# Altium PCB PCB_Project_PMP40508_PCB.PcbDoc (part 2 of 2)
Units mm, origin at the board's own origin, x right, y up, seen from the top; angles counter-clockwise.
Board outline 120 x 67 mm, 2 copper layers (Top Layer, Bottom Layer), stack 1.575 mm thick; 78 components, 43 nets, 177 pads, 0 vias.
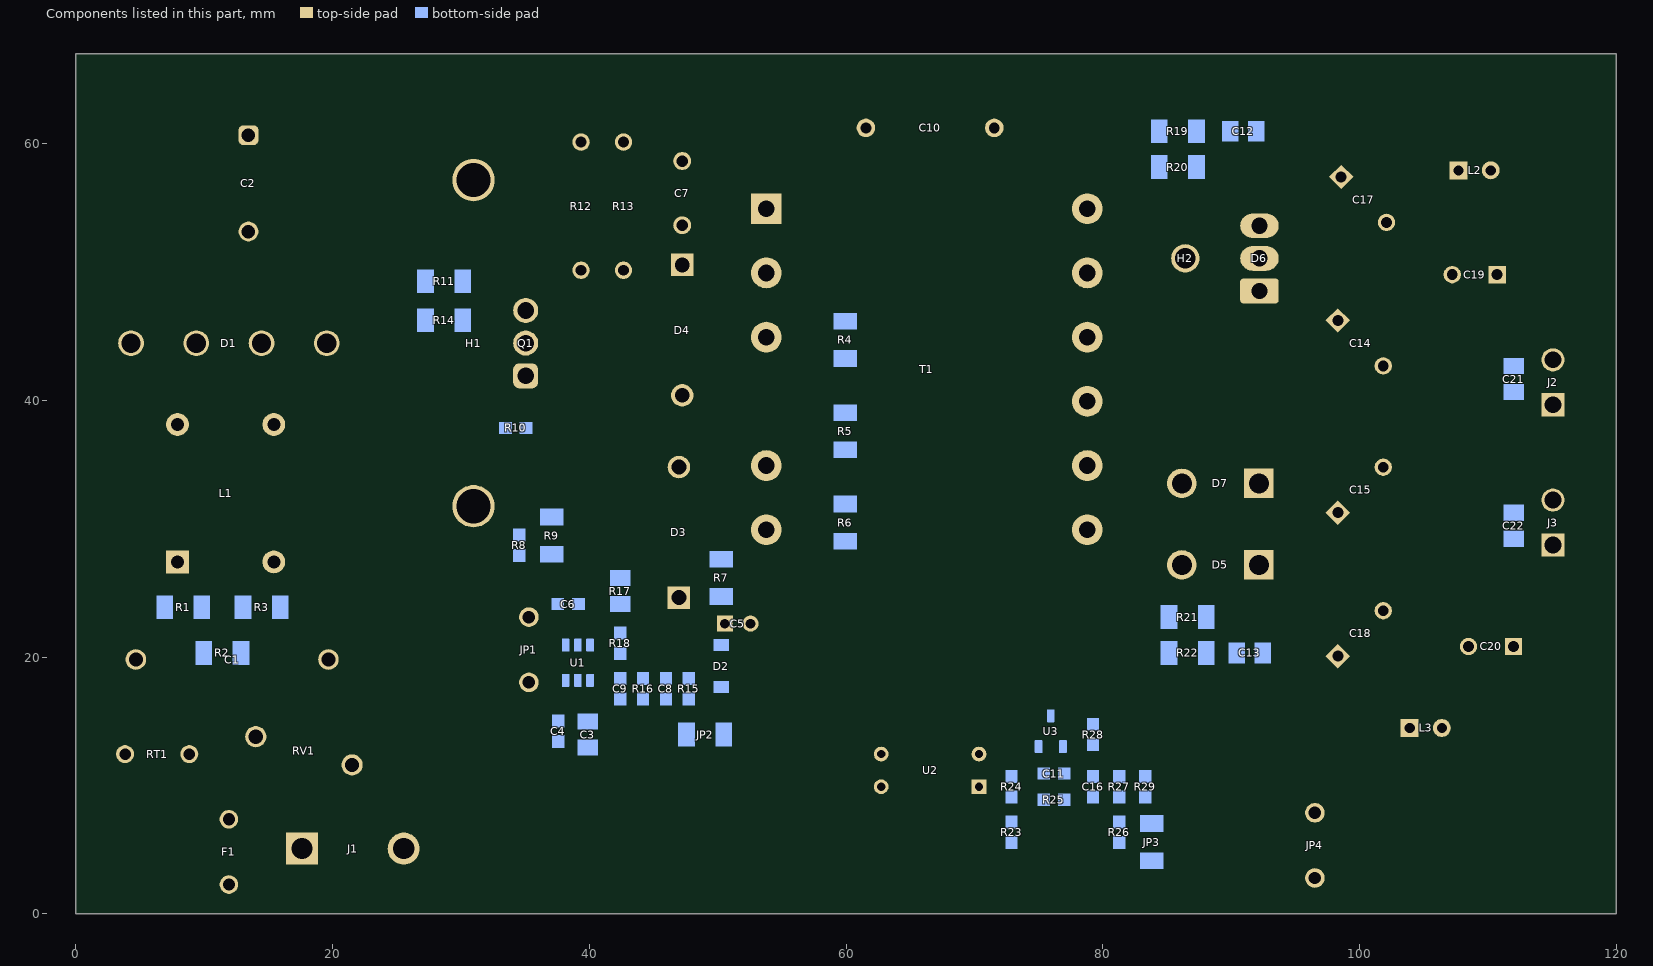
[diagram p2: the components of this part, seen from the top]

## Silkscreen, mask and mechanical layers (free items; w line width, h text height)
Top Overlay:
  text "VOUT2" at 112.776,45.466 h1.85
  text "GND" at 113.284,35.306 h1.85
  text "VOUT1" at 112.776,24.638 h1.85
  text "L" at 17.526,10.16 h1.85
  text "N" at 24.892,10.16 h1.85
  text "PMP40508 Rev. 1.0" at 40.132,5.08 h2.5
  text ".Layer_Name" at 14.656,-21.806 h1.52
Bottom Overlay:
  circle w0.254: c5,62 r3.5
  circle w0.254: c115,62 r3.5
  circle w0.254: c115,5 r3.5
  circle w0.254: c5,5 r3.5
  text ".Layer_Name" at 14.656,-21.806 h1.52
Top Paste:
  text ".Layer_Name" at 14.656,-21.806 h1.52
Bottom Paste:
  text ".Layer_Name" at 14.656,-21.806 h1.52
Top Solder:
  text ".Layer_Name" at 14.656,-21.806 h1.52
  text ".Layer_Name" at 14.656,-21.806 h1.52
Bottom Solder:
  text ".Layer_Name" at 14.656,-21.806 h1.52
Drill Guide:
  text ".Layer_Name" at 14.656,-21.806 h1.52
M1 Board Outline:
  lines w0.152: 32.512,42.926 37.338,42.926 37.338,43.434 32.512,43.434 32.512,42.926 ; 32.512,45.466 32.512,45.974 37.338,45.974 37.338,45.466 32.512,45.466 ; 66.04,6.096 67.056,6.096 67.056,16.256 66.04,16.256 66.04,6.096
  lines w0.254: 0,0 0,67 120,67 120,0 0,0
  text ".Layer_Name" at 14.656,-21.806 h1.52
M2 Board Dimensions:
  rectangle: 0,-6.985 3.175,-3.81
  rectangle: 3.175,-10.16 12.7,-6.985
  lines w0.178: 0,-6.985 25.4,-6.985 ; 3.175,-10.16 3.175,-3.81 ; 6.35,-10.16 6.35,-3.81 ; 12.7,-10.16 12.7,-3.81 ; 19.05,-10.16 19.05,-3.81 ; 0,-10.16 25.4,-10.16 25.4,-3.81 0,-3.81 0,-10.16
  text ".Layer_Name" at 14.656,-21.806 h1.52
M3 3D STEP Top:
  text ".Layer_Name" at 14.656,-21.806 h1.52
M4 3D STEP Bottom:
  text ".Layer_Name" at 14.656,-21.806 h1.52
M5 Assembly Top:
  lines w0.254: -7.417,-23.626 160.223,-23.626 ; -7.417,-18.462 160.274,-18.462 ; -7.417,-13.297 -7.417,-28.791 94.31,-28.791 160.274,-28.791 160.274,-13.297 -7.404,-13.297 -7.404,-28.791 32.614,-28.791 ; 55.194,-28.791 55.194,-13.297 ; 87.376,-18.462 87.376,-13.297 ; 108.712,-18.462 108.712,-13.297 ; 124.511,-28.956 124.511,-23.804
  text "COMPONENTS MARKED 'DNP' SHOULD NOT BE POPULATED." at 29.299,-8.09 h1.52
  text "ASSEMBLY VARIANT:" at 29.286,-11.024 h1.52
  text ".VariantName" at 55.601,-11.024 h1.52
  text "PCB VIEWED FROM TOP SIDE" at -5.804,-16.654 h1.52
  text "BOARD #:" at 57.099,-16.654 h1.52
  text ".PRJ_Number" at 70.955,-16.654 h1.52
  text "REV:" at 92.405,-16.654 h1.52
  text ".PCB_Rev" at 99.809,-16.654 h1.52
  text "SVN REV:" at 113.69,-16.654 h1.52
  text ".VersionControl_RevNumber" at 126.543,-16.654 h1.52
  text "TID #:" at 57.099,-21.819 h1.52
  text ".TID" at 70.955,-21.819 h1.52
  text "PLOT NAME =" at -5.804,-27.034 h1.52
  text ".plot_File_Name" at 14.656,-27.034 h1.52
  text "GENERATED    :" at 57.15,-27.034 h1.52
  text ".Print_Date" at 79.235,-27.034 h1.52
  text ".Print_Time" at 97.752,-27.034 h1.52
  text "TEXAS INSTRUMENTS" at 129.87,-27.034 h1.52
M6 Assembly Bottom:
  lines w0.254: -7.429,-18.474 160.261,-18.474 ; -7.379,-23.639 160.261,-23.639 ; 28.334,-28.969 28.334,-23.817 ; 44.133,-18.474 44.133,-13.31 ; 65.468,-18.474 65.468,-13.31 ; 97.65,-28.804 97.65,-13.31 ; 120.231,-28.804 160.249,-28.804 160.249,-13.31 -7.429,-13.31 -7.429,-28.804 58.534,-28.804 160.261,-28.804 160.261,-13.31
  text "COMPONENTS MARKED 'DNP' SHOULD NOT BE POPULATED." at 154.991,-8.077 h1.52
  text ".VariantName" at 128.473,-11.024 h1.52
  text "ASSEMBLY VARIANT:" at 154.864,-11.024 h1.52
  text ".VersionControl_RevNumber" at 26.302,-16.667 h1.52
  text "SVN REV:" at 39.154,-16.667 h1.52
  text ".PCB_Rev" at 53.035,-16.667 h1.52
  text "REV:" at 60.439,-16.667 h1.52
  text ".PRJ_Number" at 81.89,-16.667 h1.52
  text "BOARD #:" at 95.745,-16.667 h1.52
  text "PCB VIEWED FROM BOTTOM SIDE" at 158.648,-16.667 h1.52
  text ".TID" at 81.89,-21.831 h1.52
  text "TID #:" at 95.745,-21.831 h1.52
  text "TEXAS INSTRUMENTS" at 22.974,-27.047 h1.52
  text ".Print_Time" at 55.093,-27.047 h1.52
  text ".Print_Date" at 73.609,-27.047 h1.52
  text "GENERATED    :" at 95.694,-27.047 h1.52
  text ".plot_File_Name" at 138.189,-27.047 h1.52
  text "PLOT NAME =" at 158.648,-27.047 h1.52
M9 Title Sheet:
  drawing of 57 lines, arcs and shapes, not listed
  text "1" at 18.792,204.127 h1.78
  text "2" at 82.182,204.127 h1.78
  text "3" at 145.411,204.127 h1.78
  text "4" at 209.08,204.127 h1.78
  text "5" at 272.555,204.127 h1.78
  text "6" at 336.182,204.127 h1.78
  text "A" at -10.579,175.095 h1.78
  text "A" at 365.341,175.095 h1.78
  text "B" at -10.579,114.643 h1.78
  text "B" at 365.341,114.643 h1.78
  text "C" at -10.579,54.318 h1.78
  text "C" at 365.341,54.318 h1.78
  text "PROJECT TITLE:" at 288.125,7.048 h1.14
  text ".PRJ_Title" at 289.395,3.662 h1.78
  text "DESIGNED FOR:" at 288.125,-0.597 h1.14
  text ".PRJ_Customer" at 289.395,-4.153 h1.78
  text "D" at -10.579,-5.88 h1.78
  text "D" at 365.341,-5.88 h1.78
  text "FILE NAME:" at 288.125,-8.217 h1.14
  text ".PCB_File_Name_No_Path" at 289.395,-11.265 h1.78
  text "Texas Instruments (TI) and/or its licensors do not warrant the accuracy or completeness of this specification" at 161.9,-15.376 h1.14
  text "ENGINEER:" at 288.125,-15.583 h1.14
  text "LAYOUT BY:" at 326.352,-15.583 h1.14
  text "or any information contained therein. TI and/or its licensors do not warrant that this design will meet" at 160.757,-18.237 h1.14
  text ".PRJ_Engineer" at 289.395,-19.52 h1.78
  text ".PCB_Layout" at 327.635,-19.52 h1.78
  text "the specifications, will be suitable for your application or fit for any particular purpose, or will operate in" at 160.757,-21.099 h1.14
  text ".Layer_Name" at 14.656,-21.806 h1.52
  text "ALTIUM DESIGNER VERSION:" at 326.352,-23.457 h1.14
  text "an implementation. TI and/or its licensors do not warrant that the design is production worthy. You should" at 160.757,-23.961 h1.14
  text "completely validate and test your design implementation to confirm the system functionality for your application." at 161.9,-26.822 h1.14
  text ".print_Scale" at 289.395,-26.843 h1.78
  text ".Application_BuildNumber" at 327.635,-26.843 h1.78
  text "1" at 18.792,-32.093 h1.78
  text "2" at 82.182,-32.093 h1.78
  text "3" at 145.411,-32.093 h1.78
  text "4" at 209.08,-32.093 h1.78
  text "5" at 272.555,-32.093 h1.78
  text "6" at 336.182,-32.093 h1.78
M10 Fab Notes:
  drawing of 189 lines, arcs and shapes, not listed
  text "DESIGN INFORMATION" at 314.503,161.447 h1.52
  text "MIN. TRACK WIDTH:" at 298.131,158.091 h1.52
  text "8" at 325.976,158.091 h1.52
  text "MIL" at 329.907,158.091 h1.52
  text "MIN. CLEARANCE:" at 298.131,154.938 h1.52
  text "0.2" at 324.452,154.938 h1.52
  text "mm" at 329.907,154.938 h1.52
  text "MIN. VIA PAD SIZE:" at 298.131,151.785 h1.52
  text "24" at 325.214,151.785 h1.52
  text "MIL" at 329.907,151.785 h1.52
  text "0.05mm (2MIL)" at 315.784,148.486 h1.52
  text "MINIMUM ANNULAR RING" at 289.769,148.277 h1.52
  text "EXTERNAL" at 333.768,148.277 h1.52
  text "PER" at 294.849,145.48 h1.52
  text "IPC-D-275 CLASS 2 LEVEL C" at 300.437,145.48 h1.52
  text "MIL, HOLES" at 338.238,142.928 h1.52
  text "+/-" at 328.27,142.709 h1.52
  text "+/-" at 349.961,142.709 h1.52
  text "REGISTRATION TOLERANCES:" at 289.769,142.682 h1.52
  text "METAL" at 320.243,142.682 h1.52
  text "5" at 334.879,142.683 h1.52
  text "3" at 356.037,142.683 h1.52
  text "MIL" at 358.99,142.682 h1.52
  text "HOLE SIZE TOLERANCE (UNLESS OTHERWISE SPECIFIED):" at 289.769,140.185 h1.52
  text "+/-" at 349.961,140.112 h1.52
  text "3" at 356.037,140.085 h1.52
  text "MIL" at 358.99,140.085 h1.52
  text "MATERIAL:" at 287.87,136.589 h1.52
  text "FR-4 High Tg" at 312.926,133.324 h1.52
  text "X" at 309.257,133.122 h1.52
  text "FR-408" at 298.563,133.007 h1.52
  text "OTHER" at 336.358,133.007 h1.52
  text "62 MIL (1.6mm) +/-10%" at 306.694,129.374 h1.52
  text "X" at 303.643,129.312 h1.52
  text "THICKNESS:" at 289.769,129.165 h1.52
  text "OTHER" at 339.33,129.165 h1.52
  text "TOLERANCE:" at 289.769,125.652 h1.52
  text "X" at 311.314,125.652 h1.52
  text "ANSI IPC-6012 TYPE 3 CLASS 2" at 315.836,125.652 h1.52
  text "OTHER +/-" at 315.835,121.989 h1.52
  text "BOW & TWIST:" at 289.769,118.302 h1.52
  text "X" at 311.314,118.302 h1.52
  text "ANSI IPC-6012 TYPE 3 CLASS 2" at 315.836,118.302 h1.52
  text "OTHER +/-" at 315.835,114.576 h1.52
  text "DRILLING:" at 287.87,111.258 h1.52
  text "NC_DRILL FILES" at 332.599,108.586 h1.52
  text "REFERENCE:" at 289.769,108.486 h1.52
  text "X" at 306.463,108.484 h1.52
  text "AS SHOWN" at 310.984,108.486 h1.52
  text "X" at 329.348,108.486 h1.52
  text "OTHER" at 340.168,104.873 h1.52
  text "PTH COPPER THICKNESS:" at 289.761,104.783 h1.52
  text "X" at 318.697,104.783 h1.52
  text "20-30 um" at 321.948,104.783 h1.52
  text "BOARD FINISH:" at 287.87,101.034 h1.52
  text "SILKSCREEN:" at 291.812,98.237 h1.52
  text "X" at 316.14,98.237 h1.52
  text "TOP" at 319.112,98.237 h1.52
  text "X" at 329.094,98.237 h1.52
  text "BOTTOM" at 332.091,98.237 h1.52
  text "SILKSCREEN COLOR:" at 291.812,94.295 h1.52
  text "X" at 316.115,94.295 h1.52
  text "WHITE" at 319.112,94.295 h1.52
  text "OTHER" at 332.091,94.295 h1.52
  text "X" at 319.442,90.652 h1.52
  text "GREEN" at 322.439,90.652 h1.52
  text "OTHER" at 338.136,90.652 h1.52
  text "SOLDER RESIST COLOR:" at 291.812,90.477 h1.52
  text "X" at 319.442,86.734 h1.52
  text "MATTE" at 322.439,86.734 h1.52
  text "SEMI-GLOSS" at 338.125,86.717 h1.52
  text "IMMERSION GOLD (ENIG)" at 314.819,82.345 h1.52
  text "ENEPIG" at 348.793,82.162 h1.52
  text "SURFACE FINISH:" at 287.87,82.136 h1.52
  text "X" at 310.298,82.136 h1.52
  text "IMM. TIN/SILVER OR EQUIV" at 296.24,78.649 h1.52
  text "OTHER" at 332.599,78.549 h1.52
  text "ARRAY/PANEL:" at 287.87,74.602 h1.52
  text "CUT AND TRIM PER M1 BOARD OUTLINE" at 314.819,74.393 h1.52
  text "N.C. ROUTE" at 314.819,70.94 h1.52
  text "X" at 332.295,70.94 h1.52
  text "V. SCORE" at 336.816,70.94 h1.52
  text "CERTIFICATION:" at 287.87,67.66 h1.52
  text "MATERIALS AND WORKMANSHIP FOR ALL PCBS" at 306.285,67.66 h1.52
  text "TO MEET OR EXCEED THE REQUIREMENTS OF:" at 306.285,65.271 h1.52
  text "X" at 297.078,62.003 h1.52
  text "ANSI IPC-A-600F CLASS ->" at 300.329,62.003 h1.52
  text "X" at 342.188,62.003 h1.52
  text "2" at 344.982,62.003 h1.52
  text "1" at 336.981,61.965 h1.52
  text "3" at 353.973,61.965 h1.52
  text "X" at 317.702,58.252 h1.52
  text "RoHS" at 320.953,58.252 h1.52
  text "OTHER" at 337.321,58.252 h1.52
  text "PER ORDER" at 347.407,58.252 h1.52
  text "ALL BOARDS MUST MEET OR EXCEED UL94-V0 REQUIREMENTS." at 288.569,54.345 h1.52
  text "PCB MUST BEAR THE UL94V-0 UL REGISTERED MATERIAL ID NUMBER" at 288.569,51.397 h1.52
  text "ADDITIONAL REQUIREMENTS:" at 287.87,47.094 h1.52
  text "MICROSECTION:" at 289.769,44.373 h1.52
  text "YES" at 312.775,44.373 h1.52
  text "REQUIRED" at 334.657,40.707 h1.52
  text "BARE BOARD ELEC. TEST:" at 289.769,40.634 h1.52
  text "NONE" at 322.935,40.634 h1.52
  text "X" at 331.66,40.634 h1.52
  text "PER ORDER" at 349.693,40.634 h1.52
  text "XX MIL VIAS REQUIRE NON-CONDUCTIVE FILL AND PLANARIZE" at 294.04,35.428 h1.5
  text "XX MIL VIAS REQUIRE CONDUCTIVE FILL AND PLANARIZE" at 294.243,32.787 h1.52
  text "OUTER XX MIL TRACES REQUIRE 50 OHM SINGLE-ENDED IMPEDANCE" at 294.218,28.637 h1.47
  text "LAYER 2 & 3 (INNER LAYERS) XX MIL WIDE, XX MIL SPACE / TRACES REQUIRE 100 OHM DIFFERENTIAL IMPEDANCE" at 294.015,22.65 h1.52
  text ".Layer_Name" at 14.656,-21.806 h1.52
M11 Gerber Information:
  lines w0.254: -7.417,-23.626 160.223,-23.626 ; -7.417,-18.462 160.274,-18.462 ; -7.417,-13.297 -7.417,-28.791 94.31,-28.791 160.274,-28.791 160.274,-13.297 -7.404,-13.297 -7.404,-28.791 32.614,-28.791 ; 55.194,-28.791 55.194,-13.297 ; 87.376,-18.462 87.376,-13.297 ; 108.712,-18.462 108.712,-13.297 ; 124.511,-28.956 124.511,-23.804
  text "ALL ARTWORK VIEWED FROM TOP SIDE" at -5.804,-16.654 h1.52
  text "BOARD #:" at 57.099,-16.654 h1.52
  text ".PRJ_Number" at 70.955,-16.654 h1.52
  text "REV:" at 92.405,-16.654 h1.52
  text ".PCB_Rev" at 99.809,-16.654 h1.52
  text "SVN REV:" at 113.69,-16.654 h1.52
  text ".VersionControl_RevNumber" at 126.543,-16.654 h1.52
  text "LAYER NAME =" at -5.804,-21.806 h1.52
  text "TID #:" at 57.099,-21.819 h1.52
  text ".TID" at 70.955,-21.819 h1.52
  text "PLOT NAME =" at -5.804,-27.034 h1.52
  text ".plot_File_Name" at 14.656,-27.034 h1.52
  text "GENERATED    :" at 57.15,-27.034 h1.52
  text ".Print_Date" at 79.235,-27.034 h1.52
  text ".Print_Time" at 97.752,-27.034 h1.52
  text "TEXAS INSTRUMENTS" at 129.87,-27.034 h1.52
M12 Stackup:
  drawing of 191 lines, arcs and shapes, not listed
  text "Layer" at 248.865,198.882 h1.52
  text "Name" at 259.277,198.882 h1.52
  text "Material" at 282.892,198.882 h1.52
  text "Thickness" at 304.731,198.882 h1.52
  text "Constant" at 321.236,198.882 h1.52
  text "Board Layer Stack" at 335.711,198.882 h1.52
  text "1" at 248.865,195.834 h1.52
  text "Top Overlay" at 259.277,195.834 h1.52
  text "2" at 248.865,192.786 h1.52
  text "Top Solder" at 259.277,192.786 h1.52
  text "Solder Resist" at 282.892,192.786 h1.52
  text "0.40mil" at 304.731,192.786 h1.52
  text "3.5" at 321.236,192.786 h1.52
  text "3" at 248.865,189.738 h1.52
  text "Top Layer" at 259.277,189.738 h1.52
  text "Copper" at 282.892,189.738 h1.52
  text "1.40mil" at 304.731,189.738 h1.52
  text "4" at 248.865,186.69 h1.52
  text "Dielectric1" at 259.277,186.69 h1.52
  text "FR-4" at 282.892,186.69 h1.52
  text "59.20mil" at 304.731,186.69 h1.52
  text "4.8" at 321.236,186.69 h1.52
  text "5" at 248.865,183.642 h1.52
  text "Bottom Layer" at 259.277,183.642 h1.52
  text "Copper" at 282.892,183.642 h1.52
  text "1.40mil" at 304.731,183.642 h1.52
  text "6" at 248.865,180.594 h1.52
  text "Bottom Solder" at 259.277,180.594 h1.52
  text "Solder Resist" at 282.892,180.594 h1.52
  text "0.40mil" at 304.731,180.594 h1.52
  text "3.5" at 321.236,180.594 h1.52
  text "7" at 248.865,177.546 h1.52
  text "Bottom Overlay" at 259.277,177.546 h1.52
  text ".Layer_Name" at 14.656,-21.806 h1.52
M13 Component Bodies Top:
  text ".Layer_Name" at 14.656,-21.806 h1.52
M14 Component Bodies Bottom:
  text ".Layer_Name" at 14.656,-21.806 h1.52
M15 Courtyards Top:
  text ".Layer_Name" at 14.656,-21.806 h1.52
M16 Courtyards Bottom:
  text ".Layer_Name" at 14.656,-21.806 h1.52
Drill Drawing:
  drawing of 183 lines, arcs and shapes, not listed
  text "Symbol" at 135.778,85.864 h1.83
  text "Quantity" at 143.027,85.864 h1.83
  text "Finished Hole Size" at 151.076,85.864 h1.83
  text "Plated" at 166.853,85.864 h1.83
  text "Hole Type" at 173.051,85.864 h1.83
  text "Drill Layer Pair" at 182.194,85.864 h1.83
  text "Hole Tolerance" at 200.201,85.864 h1.83
  text "4" at 143.027,83.34 h1.52
  text "25.59mil (0.650mm)" at 151.076,83.34 h1.52
  text "PTH" at 166.853,83.34 h1.52
  text "Round" at 173.051,83.34 h1.52
  text "Top Layer - Bottom Layer" at 182.194,83.34 h1.52
  text "2" at 143.027,80.817 h1.52
  text "29.53mil (0.750mm)" at 151.076,80.817 h1.52
  text "PTH" at 166.853,80.817 h1.52
  text "Round" at 173.051,80.817 h1.52
  text "Top Layer - Bottom Layer" at 182.194,80.817 h1.52
  text "4" at 143.027,78.294 h1.52
  text "31.00mil (0.787mm)" at 151.076,78.294 h1.52
  text "PTH" at 166.853,78.294 h1.52
  text "Round" at 173.051,78.294 h1.52
  text "Top Layer - Bottom Layer" at 182.194,78.294 h1.52
  text "18" at 143.027,75.77 h1.52
  text "33.47mil (0.850mm)" at 151.076,75.77 h1.52
  text "PTH" at 166.853,75.77 h1.52
  text "Round" at 173.051,75.77 h1.52
  text "Top Layer - Bottom Layer" at 182.194,75.77 h1.52
  text "4" at 143.027,73.247 h1.52
  text "35.43mil (0.900mm)" at 151.076,73.247 h1.52
  text "PTH" at 166.853,73.247 h1.52
  text "Round" at 173.051,73.247 h1.52
  text "Top Layer - Bottom Layer" at 182.194,73.247 h1.52
  text "2" at 143.027,70.723 h1.52
  text "37.40mil (0.950mm)" at 151.076,70.723 h1.52
  text "PTH" at 166.853,70.723 h1.52
  text "Round" at 173.051,70.723 h1.52
  text "Top Layer - Bottom Layer" at 182.194,70.723 h1.52
  text "4" at 143.027,68.2 h1.52
  text "38.00mil (0.965mm)" at 151.076,68.2 h1.52
  text "PTH" at 166.853,68.2 h1.52
  text "Round" at 173.051,68.2 h1.52
  text "Top Layer - Bottom Layer" at 182.194,68.2 h1.52
  text "A" at 135.23,67.946 h1.12
  text "4" at 143.027,65.677 h1.52
  text "40.00mil (1.016mm)" at 151.076,65.677 h1.52
  text "PTH" at 166.853,65.677 h1.52
  text "Round" at 173.051,65.677 h1.52
  text "Top Layer - Bottom Layer" at 182.194,65.677 h1.52
  text "2" at 143.027,63.153 h1.52
  text "41.34mil (1.050mm)" at 151.076,63.153 h1.52
  text "PTH" at 166.853,63.153 h1.52
  text "Round" at 173.051,63.153 h1.52
  text "Top Layer - Bottom Layer" at 182.194,63.153 h1.52
  text "D" at 135.23,62.9 h1.12
  text "4" at 143.027,60.63 h1.52
  text "43.31mil (1.100mm)" at 151.076,60.63 h1.52
  text "PTH" at 166.853,60.63 h1.52
  text "Round" at 173.051,60.63 h1.52
  text "Top Layer - Bottom Layer" at 182.194,60.63 h1.52
  text "4" at 143.027,58.107 h1.52
  text "45.28mil (1.150mm)" at 151.076,58.107 h1.52
  text "PTH" at 166.853,58.107 h1.52
  text "Round" at 173.051,58.107 h1.52
  text "Top Layer - Bottom Layer" at 182.194,58.107 h1.52
  text "3" at 143.027,55.583 h1.52
  text "50.00mil (1.270mm)" at 151.076,55.583 h1.52
  text "PTH" at 166.853,55.583 h1.52
  text "Round" at 173.051,55.583 h1.52
  text "Top Layer - Bottom Layer" at 182.194,55.583 h1.52
  text "18" at 143.027,53.06 h1.52
  text "51.18mil (1.300mm)" at 151.076,53.06 h1.52
  text "PTH" at 166.853,53.06 h1.52
  text "Round" at 173.051,53.06 h1.52
  text "Top Layer - Bottom Layer" at 182.194,53.06 h1.52
  text "4" at 143.027,50.537 h1.52
  text "59.06mil (1.500mm)" at 151.076,50.537 h1.52
  text "PTH" at 166.853,50.537 h1.52
  text "Round" at 173.051,50.537 h1.52
  text "Top Layer - Bottom Layer" at 182.194,50.537 h1.52
  text "4" at 143.027,48.013 h1.52
  text "61.02mil (1.550mm)" at 151.076,48.013 h1.52
  text "PTH" at 166.853,48.013 h1.52
  text "Round" at 173.051,48.013 h1.52
  text "Top Layer - Bottom Layer" at 182.194,48.013 h1.52
  text "1" at 143.027,45.49 h1.52
  text "62.99mil (1.600mm)" at 151.076,45.49 h1.52
  text "PTH" at 166.853,45.49 h1.52
  text "Round" at 173.051,45.49 h1.52
  text "Top Layer - Bottom Layer" at 182.194,45.49 h1.52
  text "2" at 143.027,42.966 h1.52
  text "64.96mil (1.650mm)" at 151.076,42.966 h1.52
  text "PTH" at 166.853,42.966 h1.52
  text "Round" at 173.051,42.966 h1.52
  text "Top Layer - Bottom Layer" at 182.194,42.966 h1.52
  text "C" at 135.23,42.713 h1.12
  text "2" at 143.027,40.443 h1.52
  text "105.12mil (2.670mm)" at 151.076,40.443 h1.52
  text "PTH" at 166.853,40.443 h1.52
  text "Round" at 173.051,40.443 h1.52
  text "Top Layer - Bottom Layer" at 182.194,40.443 h1.52
  text "B" at 135.23,40.189 h1.12
  text "86 Total" at 143.027,37.92 h1.52
  text ".Layer_Name" at 14.656,-21.806 h1.52
M17 Embedded Cavity:
  text ".Layer_Name" at 14.656,-21.806 h1.52
M18 Embedded Assembly:
  text ".Layer_Name" at 14.656,-21.806 h1.52
M19 Embedded Keepout:
  text ".Layer_Name" at 14.656,-21.806 h1.52

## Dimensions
0,-10.16 to 25.4,-10.16 on M2 Board Dimensions
0,0 to 0,67 on M2 Board Dimensions
0,0 to 120,0 on M2 Board Dimensions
